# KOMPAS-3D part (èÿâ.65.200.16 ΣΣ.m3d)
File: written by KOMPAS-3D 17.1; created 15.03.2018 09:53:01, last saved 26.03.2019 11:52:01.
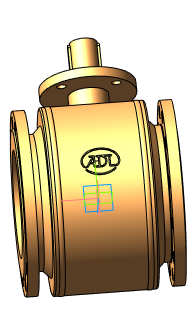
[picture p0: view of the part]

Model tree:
1. Операция без истории:2  (labels: Сталь 20  ГОСТ 1050-2013)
